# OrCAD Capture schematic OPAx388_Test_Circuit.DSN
size A; title: OPAx388 Precision, Zero-Drift, Zero-Crossover, True Rail-to-; rev: 1.4; note: Datasheet: SBOS777D EVM: N/A
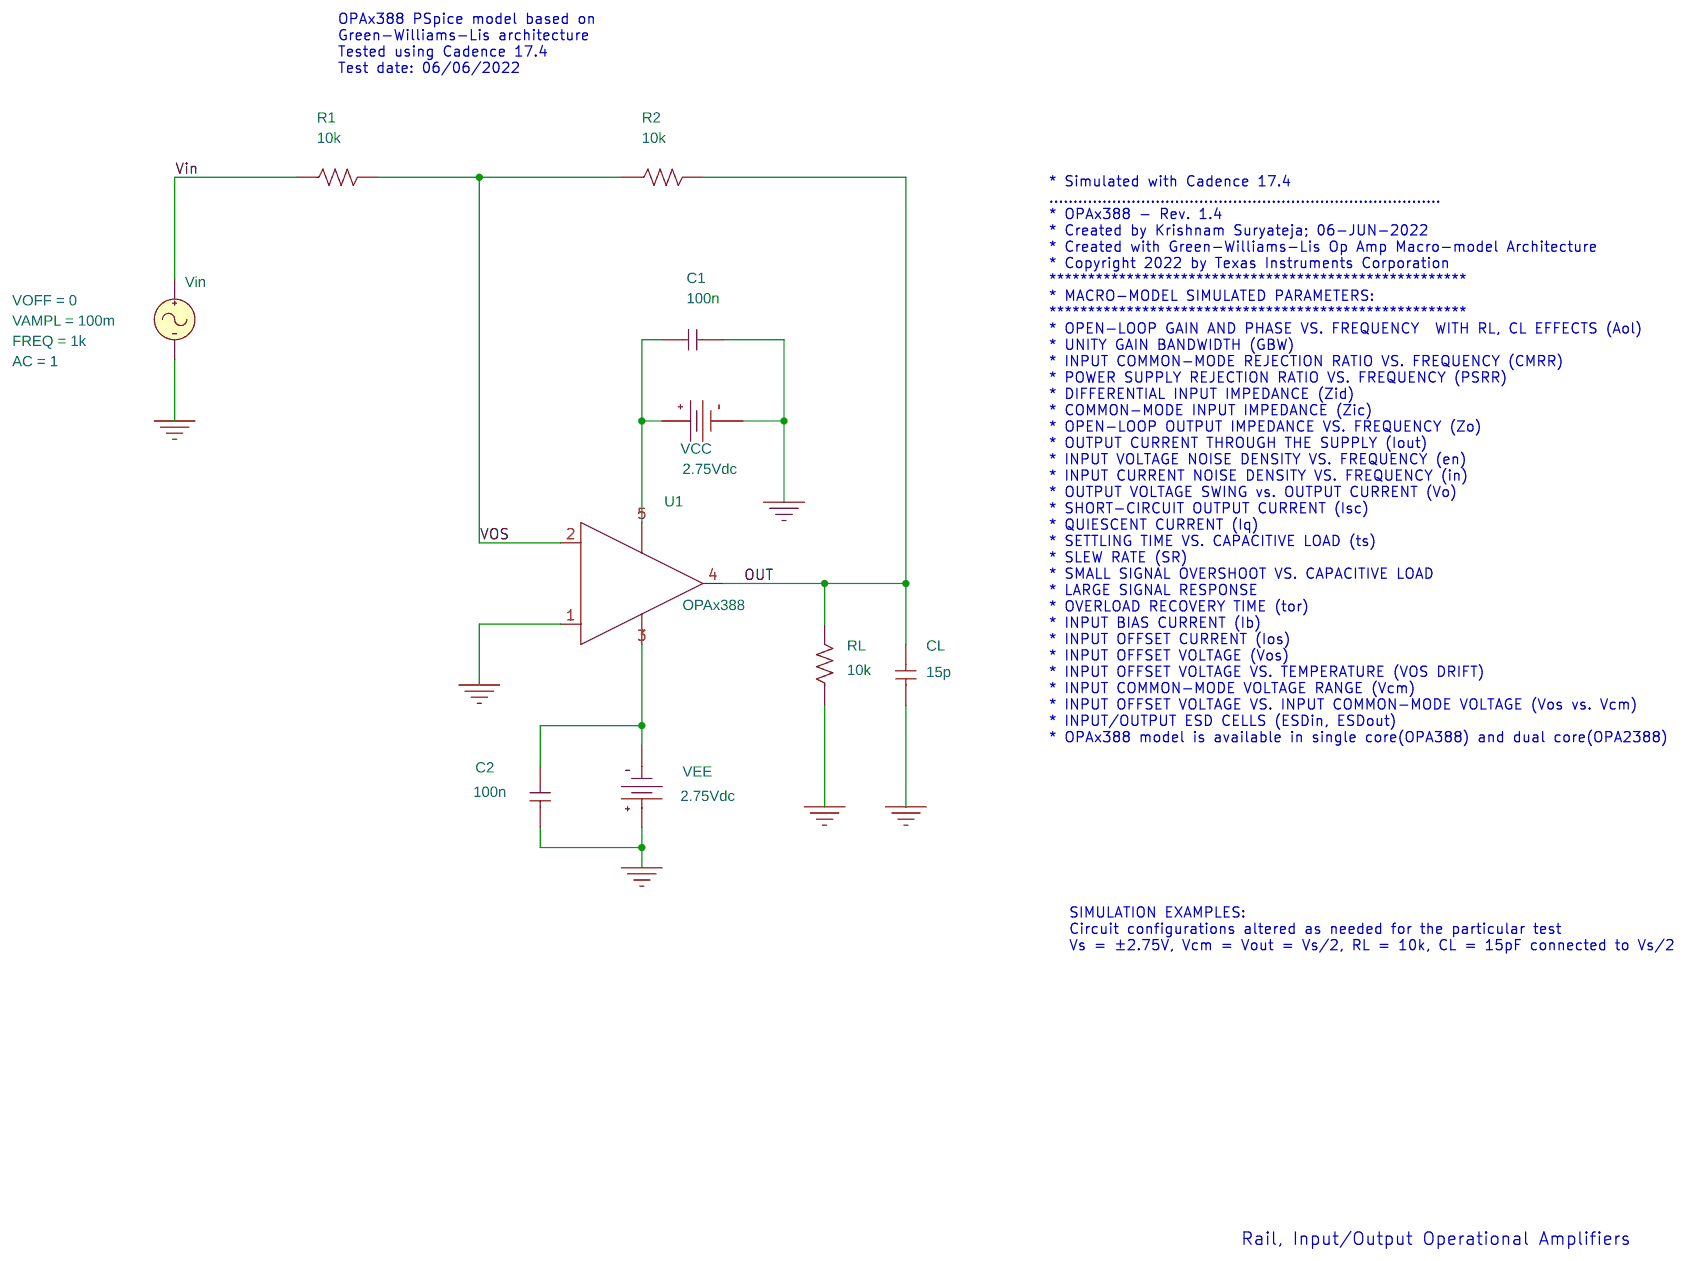
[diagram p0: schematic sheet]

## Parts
C1  100n  [cap196]
C2  100n  [cap196]
CL  15p  [cap196]
R1  10k  [AXRC05]
R2  10k  [AXRC05]
RL  10k  [AXRC05]
U1  OPAx388
VCC  VDC
VEE  VDC
Vin  VSIN

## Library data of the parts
C1 C2 CL = C
R1 R2 RL = R
U1 = OPAx388
VCC VEE = VDC: DC: 2.75Vdc
Vin = VSIN: AC: 1; FREQ: 1k; VAMPL: 100m; VOFF: 0

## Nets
Vin: R1.1 Vin.1(+)
0: C1.2 C2.1 CL.2 RL.1 U1.1(+) VCC.1(-) VEE.0(+) Vin.2(-)
OUT: CL.1 R2.2 RL.2 U1.4(OUT)
VOS: R1.2 R2.1 U1.2(-)
N27303: C1.1 U1.5(V+) VCC.0(+)
N27354: C2.2 U1.3(V-) VEE.1(-)

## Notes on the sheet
- OPAx388 PSpice model based on
  Green-Williams-Lis architecture
  Tested using Cadence 17.4
  Test date: 06/06/2022
- * Simulated with Cadence 17.4
  .................................................................................
  * OPAx388 - Rev. 1.4
  * Created by Krishnam Suryateja; 06-JUN-2022
  * Created with Green-Williams-Lis Op Amp Macro-model Architecture
  * Copyright 2022 by Texas Instruments Corporation
  ******************************************************
  * MACRO-MODEL SIMULATED PARAMETERS:
  ******************************************************
  * OPEN-LOOP GAIN AND PHASE VS. FREQUENCY  WITH RL, CL EFFECTS (Aol)
  * UNITY GAIN BANDWIDTH (GBW)
  * INPUT COMMON-MODE REJECTION RATIO VS. FREQUENCY (CMRR)
  * POWER SUPPLY REJECTION RATIO VS. FREQUENCY (PSRR)
  * DIFFERENTIAL INPUT IMPEDANCE (Zid)
  * COMMON-MODE INPUT IMPEDANCE (Zic)
  * OPEN-LOOP OUTPUT IMPEDANCE VS. FREQUENCY (Zo)
  * OUTPUT CURRENT THROUGH THE SUPPLY (Iout)
  * INPUT VOLTAGE NOISE DENSITY VS. FREQUENCY (en)
  * INPUT CURRENT NOISE DENSITY VS. FREQUENCY (in)
  * OUTPUT VOLTAGE SWING vs. OUTPUT CURRENT (Vo)
  * SHORT-CIRCUIT OUTPUT CURRENT (Isc)
  * QUIESCENT CURRENT (Iq)
  * SETTLING TIME VS. CAPACITIVE LOAD (ts)
  * SLEW RATE (SR)
  * SMALL SIGNAL OVERSHOOT VS. CAPACITIVE LOAD
  * LARGE SIGNAL RESPONSE
  * OVERLOAD RECOVERY TIME (tor)
  * INPUT BIAS CURRENT (Ib)
  * INPUT OFFSET CURRENT (Ios)
  * INPUT OFFSET VOLTAGE (Vos)
  * INPUT OFFSET VOLTAGE VS. TEMPERATURE (VOS DRIFT)
  * INPUT COMMON-MODE VOLTAGE RANGE (Vcm)
  * INPUT OFFSET VOLTAGE VS. INPUT COMMON-MODE VOLTAGE (Vos vs. Vcm)
  * INPUT/OUTPUT ESD CELLS (ESDin, ESDout)
  * OPAx388 model is available in single core(OPA388) and dual core(OPA2388)
- SIMULATION EXAMPLES:
  Circuit configurations altered as needed for the particular test
  Vs = ±2.75V, Vcm = Vout = Vs/2, RL = 10k, CL = 15pF connected to Vs/2
- Rail, Input/Output Operational Amplifiers
